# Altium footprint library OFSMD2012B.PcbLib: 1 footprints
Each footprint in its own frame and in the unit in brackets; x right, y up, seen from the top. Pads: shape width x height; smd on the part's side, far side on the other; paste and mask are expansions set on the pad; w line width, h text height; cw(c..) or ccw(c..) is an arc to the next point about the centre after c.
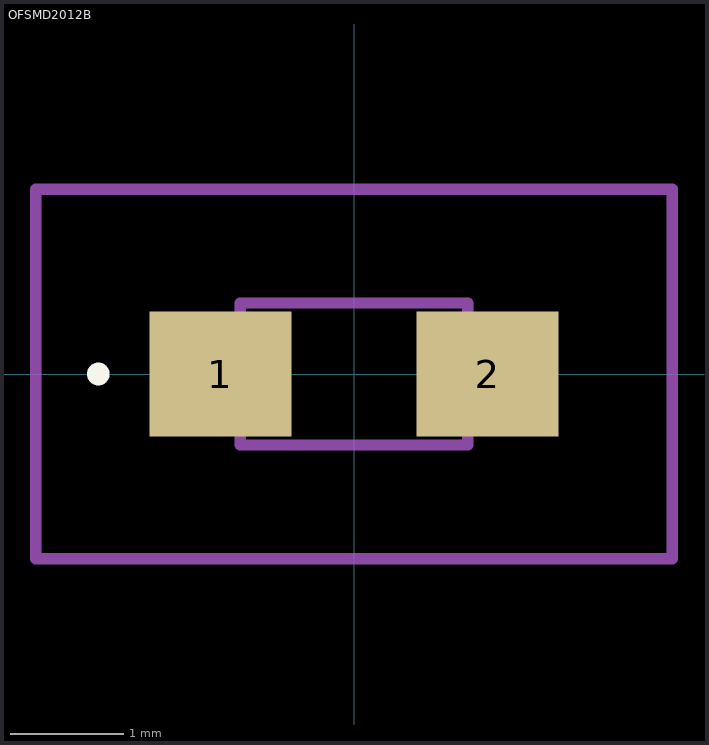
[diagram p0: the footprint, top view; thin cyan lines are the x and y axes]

## OFSMD2012B [mm]
pads (2):
  rect 1.25x1.1 smd: 1(-1.175,0) 2(1.175,0)
Top Overlay:
  lines w0.1: -2.3,0 cw(c-2.25,0) -2.2,0 ; -2.3,0 -2.3,0 ; -2.3,0 ccw(c-2.25,0) -2.2,0 ; -2.2,0 -2.2,0
Mechanical 15:
  lines w0.1: -1,-0.625 1,-0.625 1,0.625 -1,0.625 -1,-0.625
Mechanical 20:
  lines w0.1: -2.8,-1.625 2.8,-1.625 2.8,1.625 -2.8,1.625 -2.8,-1.625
